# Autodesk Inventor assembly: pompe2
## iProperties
Shininess: 21.0
Length Units: 11269
Angle Units: 11279
Time Units: 11290
Mass Units: 11283
Length Display Precision: 3
Angle Display Precision: 2
Compacted: True
Created: 2002-01
Part Number: pompe2
Document SubType Name: Assemblage
Designer: pichon
Density: 0.0
Volumn: 0.0
Area: 0.0
PropertySet Name: Model Information
Control State: 0
Master: False
Checked Out: False
Author: pichon
